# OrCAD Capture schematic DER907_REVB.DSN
size B; rev: A
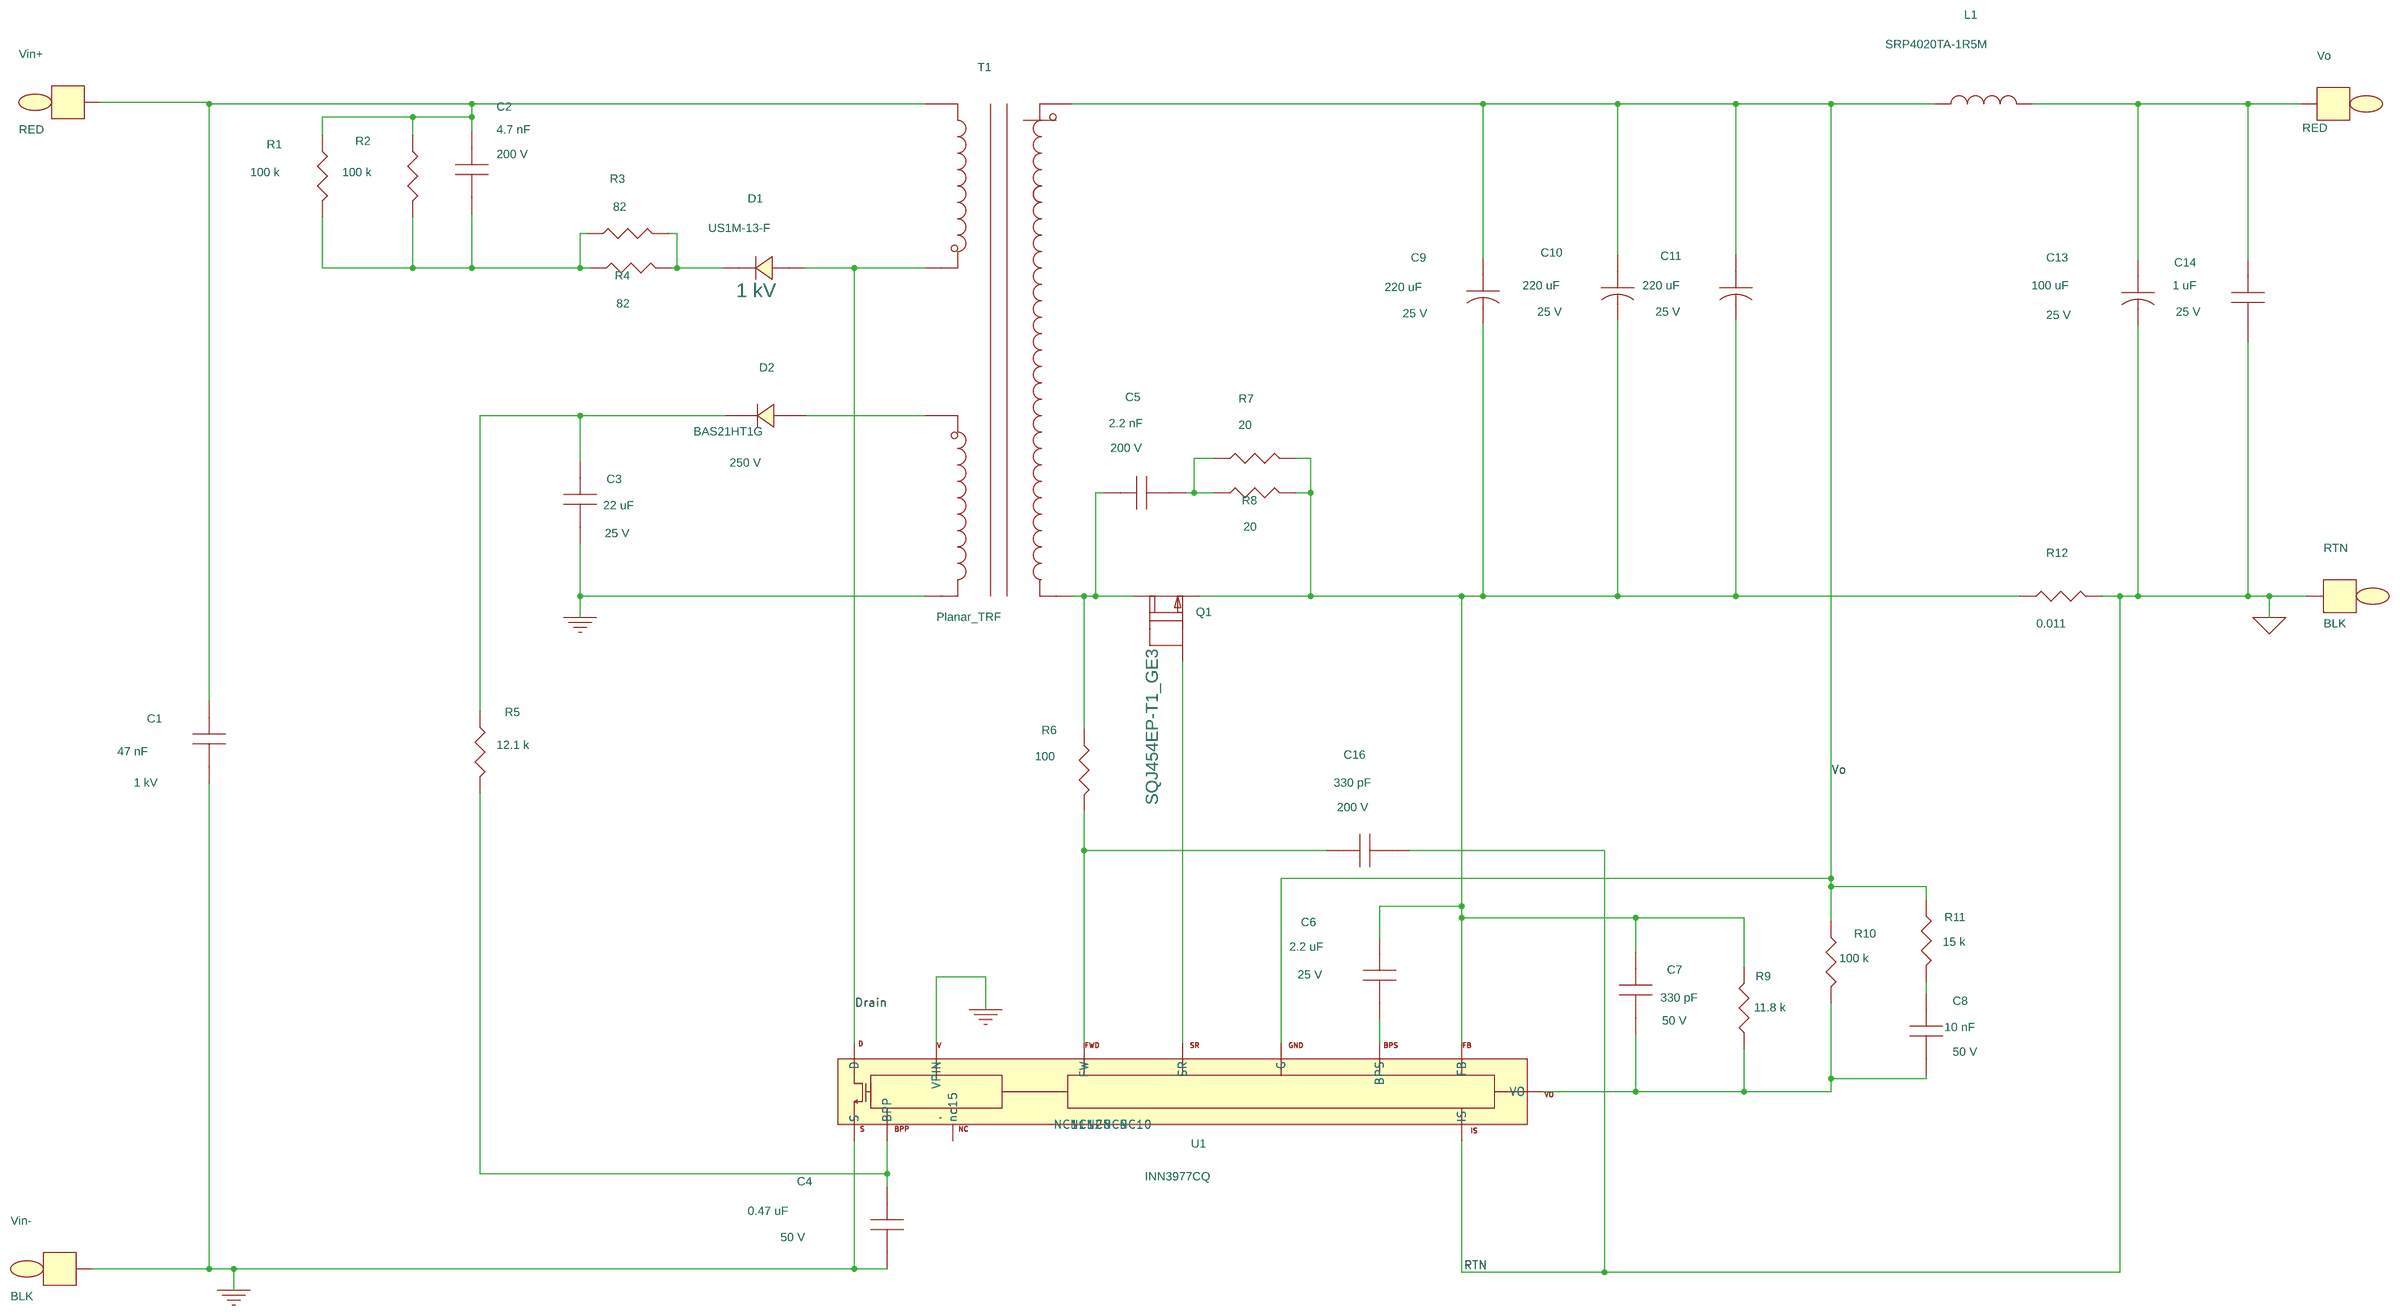
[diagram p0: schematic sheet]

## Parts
C1  47 nF  [pismc1812]
C2  4.7 nF  [pismc1206]
C3  22 uF  [pismc1206]
C4  0.47 uF  [pismc0805]
C5  2.2 nF  [pismc0805]
C6  2.2 uF  [pismc0805]
C7  330 pF  [pismc0603]
C8  10 nF  [pismc0805]
C9  220 uF  [pismcUCC_F80alelect]
C10  220 uF  [pismcUCC_F80alelect]
C11  220 uF  [pismcUCC_F80alelect]
C13  100 uF  [pismcUCC_F80alelect]
C14  1 uF  [pismc1206]
C16  330 pF  [pismc0603]
D1  US1M-13-F  [pismdsma]
D2  BAS21HT1G  [pismsod323]
L1  SRP4020TA-1R5M  [pi_sm_2-smd]
Q1  SQJ454EP-T1_GE3  [pismpqfn5x6b]
R1  100 k  [pismr1206]
R2  100 k  [pismr1206]
R3  82  [pismr1206]
R4  82  [pismr1206]
R5  12.1 k  [pismr0805]
R6  100  [pismr0603]
R7  20  [pismr1206]
R8  20  [pismr1206]
R9  11.8 k  [pismr0805]
R10  100 k  [pismr0805]
R11  15 k  [pismr0805]
R12  0.011  [pismr1206]
RTN  BLK  [pitpkeystone125x125]
T1  Planar_TRF  [pi_PlanarXfrmr_30W_Payton]
U1  INN3977CQ  [pi_ic_insop_24D]
Vin+  RED  [pitpkeystone125x125]
Vin-  BLK  [pitpkeystone125x125]
Vo  RED  [pitpkeystone125x125]

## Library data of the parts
C1 = CAP_NP: Disp_Voltage: 1 kV; Part Number: 20-09232-00; Voltage: 1000V
C2 = CAP_NP: Disp_Voltage: 200 V; Part Number: 20-09231-00; Voltage: 200 V
C3 = CAP_NP: Disp_Voltage: 25 V; Part Number: 20-09236-00; Voltage: 25 V
C4 = CAP_NP: Disp_Voltage: 50 V; Part Number: 20-09197-00; Voltage: 50 V
C5 = CAP_NP: Disp_Voltage: 200 V; Part Number: 20-09233-00; Voltage: 200 V
C6 = CAP_NP: Disp_Voltage: 25 V; Part Number: 20-08603-00; Voltage: 25 V
C7 = CAP_NP: ALT_SYMBOLS: pismc0603_1; Disp_Voltage: 50 V; FPLIST: pismc0603,pismc0603_1; Part Number: 20-09235-00; Voltage: 50 V
C8 = CAP_NP: Disp_Voltage: 50 V; Part Number: 20-00965-00; Voltage: 50 V
C9-C11 = CAP_POL: Disp_Voltage: 25 V; Part Number: 23-00069-00; Voltage: 25 V
C13 = CAP_POL: Disp_Voltage: 25 V; Part Number: 23-00070-00; Voltage: 25 V
C14 = CAP_NP: Disp_Voltage: 25 V; Part Number: 20-00897-00; Voltage: 25 V
C16 = CAP_NP: Disp_Voltage: 200 V; Part Number: 20-01392-00; Voltage: 200 V
D1 = DIODE: Part Number: 15-00957-00; VA: 1 kV
D2 = DIODE: ALT_SYMBOLS: pismsod323_1; Disp_Voltage: 250 V; FPLIST: pismsod323,pismsod323_1; Part Number: 15-01247-00
L1 = INDUCTOR: Part Number: 30-04112-00
Q1 = FET_N_SGD_123_4_5678: Part Number: 50-00293-00
R1 R2 = R: Disp_Tol: 1%; Part Number: 05-00385-00
R3 R4 = R: Part Number: 05-01326-00
R5 = R: Disp_Tol: 1%; Part Number: 05-00692-00
R6 = R: Disp_Tol: 1%; Part Number: 05-06543-00
R7 R8 = R: Disp_Tol: 1%; Part Number: 05-00030-00
R9 = R: Disp_Tol: 1%; Part Number: 05-00691-00
R10 = R: Disp_Tol: 1%; Part Number: 05-00780-00
R11 = R: Part Number: 05-01547-00
R12 = R: Disp_Power: 1 W; Disp_Tol: 1%; Part Number: 05-06466-00
RTN Vin- = TESTPOINT: Part Number: 35-00042-00
T1 = PlanarXfrmr_30W_Payton_6: Part Number: 25-01176-00
U1 = Inno3AQ_P15_2: Part Number: 10-01245-00
Vin+ Vo = TESTPOINT: Part Number: 35-00043-00

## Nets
GND: C1.2 C3.2 C4.2 T1.1 U1.13(VPIN) U1.16(S) Vin-.1
GND SIGNAL: C13.2 C14.2 C16.2 R12.2 RTN.1 U1.1(IS)
Drain: D1.2 T1.3 U1.24(D)
NC8: U1.8(NC8)
NC9: U1.9(NC9)
NC10: U1.10(NC10)
NC11: U1.11(NC11)
NC12: U1.12(NC12)
Vo: C9.1 C10.1 C11.1 L1.1 R10.1 R11.1 T1.6 U1.2(G)
N37213: C1.1 C2.1 R1.1 R2.1 T1.2 Vin+.1
N37461: C5.2 R7.1 R8.1
N37469: C6.1 C7.1 C9.2 C10.2 C11.2 Q1.1(S) R7.2 R8.2 R9.2 R12.1 U1.3(FB)
N38055: C3.1 D2.1 R5.1
N38181: C16.1 R6.2 U1.7(FW)
N38189: C4.1 R5.2 U1.14(BPP)
N51802: C13.1 C14.1 L1.2 Vo.1
N100534: C2.2 R1.2 R2.2 R3.1 R4.1
N100538: D1.1 R3.2 R4.2
N101873: D2.2 T1.4
N103221: C5.1 Q1.5(D) R6.1 T1.5
N108532: C6.2 U1.4(BPS)
N108749: C7.2 C8.2 R9.1 R10.2 U1.6(VO)
N109833: C8.1 R11.2
N115689: Q1.4(G) U1.5(SR)

Not connected (* = marked no-connect by the designer): Q1 2(S2) 3(S3) 6(D6) 7(D7) 8(D8); U1 15(nc15)
